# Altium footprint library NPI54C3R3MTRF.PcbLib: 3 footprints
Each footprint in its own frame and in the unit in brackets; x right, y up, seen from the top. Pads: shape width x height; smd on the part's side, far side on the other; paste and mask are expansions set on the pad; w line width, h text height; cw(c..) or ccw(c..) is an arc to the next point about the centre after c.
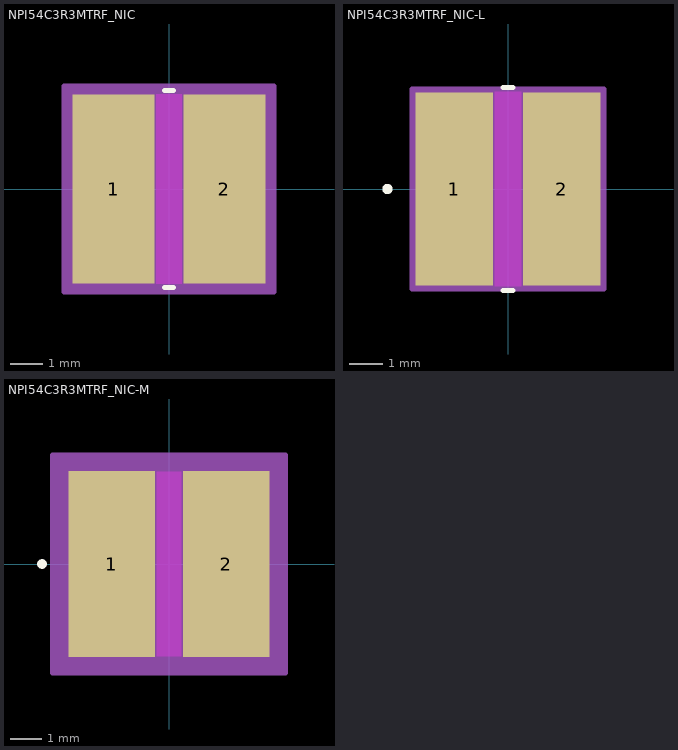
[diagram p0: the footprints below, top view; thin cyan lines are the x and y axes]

## NPI54C3R3MTRF_NIC [mil]
pads (2):
  rect 99x228 smd paste+0 mask+0: 1(-66.86,0) 2(66.86,0)
Top Layer keep-out:
  region: -15.36,-112 -15.36,112 15.36,112 15.36,-112
Top Overlay:
  lines w6: -5.25,-119 5.25,-119 ; -5.25,119 5.25,119
Keep-Out Layer:
  region: -15.36,-114 -15.36,114 15.36,114 15.36,-114
Mechanical 13:
  circle w0: c-61.86,0 r0
  lines w1: -102.36,-114 -102.36,114 ; -102.36,-114 -17.36,-114 -17.36,114 -102.36,114 ; -102.36,-114 102.36,-114 ; -102.36,-114 -102.36,114 ; -102.36,114 102.36,114 ; 102.36,-114 17.36,-114 17.36,114 102.36,114 ; 102.36,-114 102.36,114 ; 102.36,-114 102.36,114
Mechanical 15:
  region: 126.36,-124 -126.36,-124 -126.36,124 126.36,124
  lines w6: -126.36,-124 -126.36,124 126.36,124 126.36,-124 -126.36,-124
3D body "NPI54C3R3MTRF_NIC.step": height 177.01, standoff 0, extent -102.36,-114.02 102.36,114.02

## NPI54C3R3MTRF_NIC-L [mil]
pads (2):
  rect 91x226 smd paste+0 mask+0: 1(-62.86,0) 2(62.86,0)
Top Layer keep-out:
  region: -15.36,-112 -15.36,112 15.36,112 15.36,-112
Top Overlay:
  circle w6: c-141.36,0 r3
  lines w6: -5.72,-119 5.72,-119 ; -5.72,119 5.72,119
Keep-Out Layer:
  region: -15.36,-114 -15.36,114 15.36,114 15.36,-114
Mechanical 13:
  circle w0: c-57.86,0 r3
  lines w1: -102.36,-114 -102.36,114 ; -102.36,-114 -17.36,-114 -17.36,114 -102.36,114 ; -102.36,-114 102.36,-114 ; -102.36,-114 -102.36,114 ; -102.36,114 102.36,114 ; 102.36,-114 17.36,-114 17.36,114 102.36,114 ; 102.36,-114 102.36,114 ; 102.36,-114 102.36,114
Mechanical 15:
  region: 112.36,-117 -112.36,-117 -112.36,117 112.36,117
  lines w6: -112.36,-117 -112.36,117 112.36,117 112.36,-117 -112.36,-117
3D body "NPI54C3R3MTRF_NIC.step": height 177.01, standoff 0, extent -102.36,-114.02 102.36,114.02

## NPI54C3R3MTRF_NIC-M [mil]
pads (2):
  rect 107x230 smd paste+0 mask+0: 1(-70.86,0) 2(70.86,0)
Top Layer keep-out:
  region: -15.36,-112 -15.36,112 15.36,112 15.36,-112
Top Overlay:
  circle w6: c-157.36,0 r3
Keep-Out Layer:
  region: -15.36,-114 -15.36,114 15.36,114 15.36,-114
Mechanical 13:
  circle w0: c-65.86,0 r3
  lines w1: -102.36,-114 -102.36,114 ; -102.36,-114 -17.36,-114 -17.36,114 -102.36,114 ; -102.36,-114 102.36,-114 ; -102.36,-114 -102.36,114 ; -102.36,114 102.36,114 ; 102.36,-114 17.36,-114 17.36,114 102.36,114 ; 102.36,-114 102.36,114 ; 102.36,-114 102.36,114
Mechanical 15:
  region: 144.36,-135 -144.36,-135 -144.36,135 144.36,135
  lines w6: -144.36,-135 -144.36,135 144.36,135 144.36,-135 -144.36,-135
3D body "NPI54C3R3MTRF_NIC.step": height 177.01, standoff 0, extent -102.36,-114.02 102.36,114.02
